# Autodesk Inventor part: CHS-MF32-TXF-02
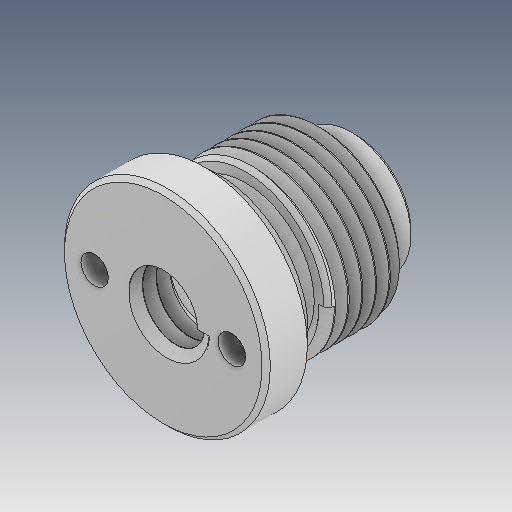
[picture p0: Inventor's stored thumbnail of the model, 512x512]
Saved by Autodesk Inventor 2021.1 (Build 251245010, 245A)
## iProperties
Created: 2021-05
Part Number: CHS-MF32-TXF-02
Material: Ogólny
Document SubType Name: Modeling
Designer: user
Density: 1 g/cm^3
Appearance: Domyślna
Author: user
Revision Number: ÈÎºÎ
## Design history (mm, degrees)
feature "ÊäÈë1"
node "Bryła1"
